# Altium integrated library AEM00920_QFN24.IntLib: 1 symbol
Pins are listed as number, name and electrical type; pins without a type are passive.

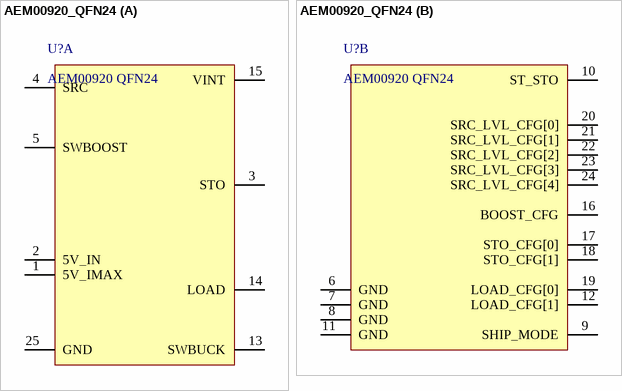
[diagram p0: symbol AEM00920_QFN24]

## AEM00920_QFN24
designator U?, comment AEM00920 QFN24
footprint QFN24_4x4mm_PITCH_0.5mm_PAD_2.7mm_QP235-00052 (QFN, 24-Leads, Body 4.00x4.00mm, Pitch 0.50mm, Thermal Pad 2.70x2.70mm, IPC High Density)
part A pins: 1 5V_IMAX, 2 5V_IN, 3 STO, 4 SRC, 5 SWBOOST, 13 SWBUCK, 14 LOAD, 15 VINT, 25 GND
part B pins: 6 GND, 7 GND, 8 GND, 9 SHIP_MODE, 10 ST_STO, 11 GND, 12 LOAD_CFG[1], 16 BOOST_CFG, 17 STO_CFG[0], 18 STO_CFG[1], 19 LOAD_CFG[0], 20 SRC_LVL_CFG[0], 21 SRC_LVL_CFG[1], 22 SRC_LVL_CFG[2], 23 SRC_LVL_CFG[3], 24 SRC_LVL_CFG[4]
